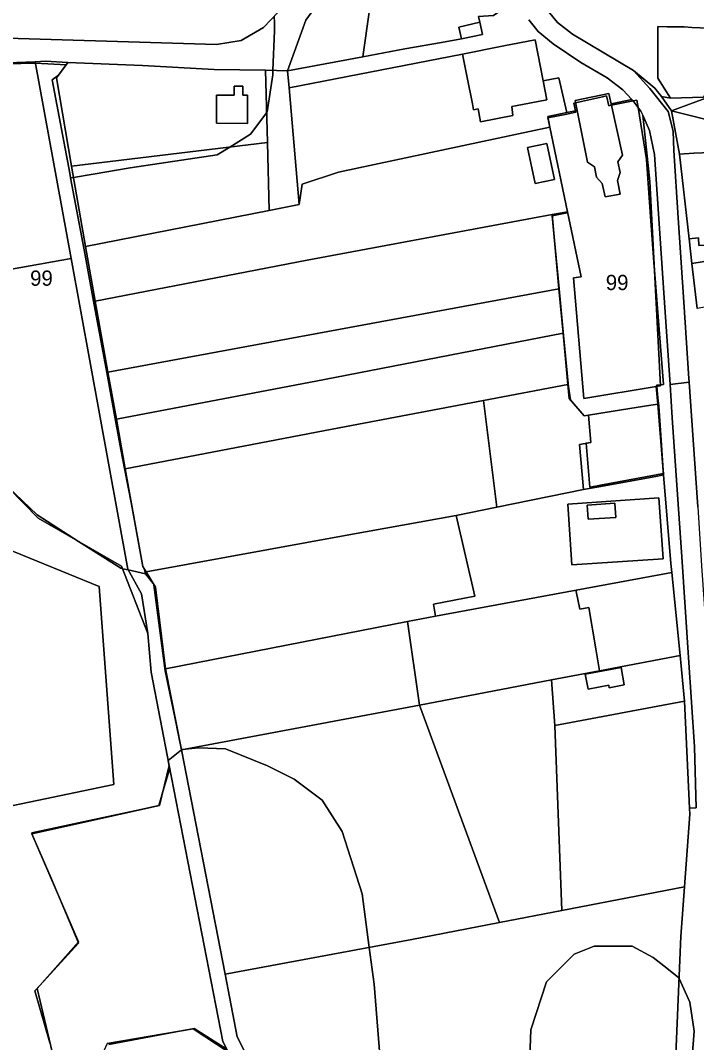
# Model space of a CAD drawing. Extents: x -522079 to -518833, y -1142400 to -1139961.
# Drawn here: x -520504.9 to -520283.3, y -1141508 to -1141173.1 of the extents above; entities that cross this region are included whole.
import ezdxf

# ---------------------------------------------------------------- set-up
doc = ezdxf.new("R2010")
doc.units = 0
for name, color, linetype in [('95560013', 7, 'Continuous'), ('95590013', 7, 'Continuous'), ('95610013', 7, 'Continuous'), ('95630013', 7, 'Continuous'), ('95640013', 7, 'Continuous'), ('95660013', 7, 'Continuous')]:
    doc.layers.add(name, color=color, linetype=linetype)

msp = doc.modelspace()

# ---------------------------------------------------------------- linework, layer by layer
at = {"layer": '95560013'}
for points in [[(-520400.61, -1141222.82), (-520331.36, -1141208.07), (-520325.59, -1141235.8), (-520330.62, -1141236.74), (-520410.93, -1141251.63), (-520480.37, -1141265.08), (-520483.58, -1141247.19), (-520423.33, -1141235.38), (-520413.51, -1141233.43), (-520412.54, -1141226.76)], [(-520423.33, -1141235.38), (-520483.58, -1141247.19), (-520488.14, -1141220.84), (-520423.9, -1141213.13)], [(-520336.17, -1141226.59), (-520329.89, -1141225.22), (-520332.41, -1141213.42), (-520338.66, -1141214.74)], [(-520330.62, -1141236.74), (-520328.39, -1141261.02), (-520407.05, -1141275.59), (-520476.2, -1141288.34), (-520480.37, -1141265.08), (-520410.93, -1141251.63)], [(-520476.2, -1141288.34), (-520407.05, -1141275.59), (-520328.39, -1141261.02), (-520327.05, -1141275.53), (-520405.18, -1141290.79), (-520473.45, -1141303.71)], [(-520405.18, -1141290.79), (-520327.05, -1141275.53), (-520325.5, -1141292.44), (-520353.1, -1141297.63), (-520402.69, -1141307.02), (-520470.52, -1141320.08), (-520473.45, -1141303.71)], [(-520353.1, -1141297.63), (-520348.74, -1141332.58), (-520362.13, -1141335.31), (-520397.21, -1141341.61), (-520463.71, -1141353.8), (-520464.8, -1141352.03), (-520470.52, -1141320.08), (-520402.69, -1141307.02)], [(-520368.84, -1141368.35), (-520378.01, -1141370.07), (-520457.31, -1141385.57), (-520460.62, -1141358.83), (-520463.71, -1141353.8), (-520397.21, -1141341.61), (-520362.13, -1141335.31), (-520355.94, -1141361.7), (-520369.53, -1141364.42)], [(-520457.31, -1141385.57), (-520378.01, -1141370.07), (-520374.09, -1141397.41), (-520388.13, -1141400.07), (-520452.14, -1141412.08)], [(-520329.77, -1141404.14), (-520327.5, -1141464.71), (-520347.92, -1141468.69), (-520374.09, -1141397.41), (-520330.86, -1141389.2)], [(-520347.92, -1141468.69), (-520376.59, -1141474.28), (-520437.82, -1141485.59), (-520452.14, -1141412.08), (-520388.13, -1141400.07), (-520374.09, -1141397.41)], [(-520438.53, -1141507.64), (-520436.83, -1141511), (-520448.25, -1141503.52), (-520476.51, -1141508.33), (-520485.33, -1141527.78), (-520494.54, -1141511.04), (-520499.43, -1141490.33), (-520485.81, -1141474.99), (-520501.13, -1141439.65), (-520459.35, -1141430.33), (-520456.11, -1141417.28)], [(-520287.25, -1141456.97), (-520288.42, -1141473.23), (-520290.19, -1141514.57), (-520290.52, -1141595.71), (-520355.96, -1141608.22), (-520447.63, -1141624.46), (-520447.82, -1141603.5), (-520446.02, -1141598.19), (-520414.26, -1141558.37), (-520414.56, -1141544.64), (-520433.82, -1141506.13), (-520437.82, -1141485.59), (-520376.59, -1141474.28), (-520347.92, -1141468.69), (-520327.5, -1141464.71)]]:
    msp.add_lwpolyline(points, close=True, dxfattribs=at)
at = {"layer": '95590013'}
for points in [[(-520392.71, -1141184.99), (-520390.51, -1141169.6), (-520385.67, -1141162.39), (-520383.02, -1141163.15), (-520382.54, -1141163.3), (-520381.05, -1141158.47), (-520376.18, -1141142.7), (-520369.8, -1141141.08), (-520369.36, -1141147.79), (-520364.41, -1141148.17), (-520363.98, -1141154.29), (-520356.57, -1141153.77), (-520356.59, -1141153.47), (-520347.81, -1141152.92), (-520346.65, -1141169.3), (-520349.86, -1141171.48), (-520354.71, -1141171.83), (-520354.34, -1141173.71), (-520361.25, -1141175.35), (-520360.34, -1141179.18), (-520366.93, -1141180.34), (-520378.86, -1141182.41)], [(-520417.36, -1141189.63), (-520411.3, -1141173.03), (-520402.63, -1141160.92), (-520399.1, -1141160.34), (-520393.37, -1141144.49), (-520399.12, -1141167.44), (-520392.92, -1141168.99), (-520390.51, -1141169.6), (-520392.71, -1141184.99)], [(-520358.48, -1141191.76), (-520356.77, -1141200.4), (-520356.39, -1141202.36), (-520354.91, -1141202.07), (-520354.06, -1141206.38), (-520343.47, -1141204.29), (-520343.86, -1141201.29), (-520342.6, -1141201.05), (-520332.37, -1141199.14), (-520333.6, -1141192.88), (-520328.4, -1141191.92), (-520325.76, -1141203.31), (-520332.09, -1141204.58), (-520331.36, -1141208.07), (-520400.61, -1141222.82), (-520412.54, -1141226.76), (-520413.51, -1141233.43), (-520416.76, -1141195.21), (-520359.99, -1141184.11)], [(-520493.12, -1141191.96), (-520489.31, -1141186.91), (-520464.88, -1141187.85), (-520441.37, -1141189.15), (-520424.53, -1141189.37), (-520423.9, -1141213.13), (-520488.14, -1141220.84)], [(-520423.33, -1141235.38), (-520423.9, -1141213.13), (-520424.53, -1141189.37), (-520417.36, -1141189.63), (-520416.76, -1141195.21), (-520413.51, -1141233.43)], [(-520432.03, -1141197.59), (-520432, -1141194.68), (-520434.8, -1141194.69), (-520434.81, -1141197.59), (-520440.66, -1141197.58), (-520440.68, -1141206.8), (-520430.51, -1141206.85), (-520430.48, -1141197.6)], [(-520281.5, -1141252.18), (-520284.8, -1141252.79), (-520285.74, -1141244.64), (-520282.66, -1141244.34), (-520282.52, -1141246.89), (-520278.03, -1141246.64), (-520278.18, -1141243.9), (-520274.53, -1141243.54), (-520253.62, -1141239.61), (-520253.52, -1141236.33), (-520252.79, -1141247.01), (-520269.34, -1141249.93)], [(-520325.09, -1141296.95), (-520320.11, -1141302.71), (-520318.74, -1141302.49), (-520317.9, -1141311.37), (-520321.67, -1141312.05), (-520320.3, -1141326.77), (-520348.74, -1141332.58), (-520353.1, -1141297.63), (-520325.5, -1141292.44)], [(-520355.94, -1141361.7), (-520362.13, -1141335.31), (-520348.74, -1141332.58), (-520320.3, -1141326.77), (-520313.48, -1141325.64), (-520296.08, -1141322.39), (-520294.09, -1141322.02), (-520291.7, -1141351.03), (-520291.41, -1141353.94), (-520322.8, -1141359.78), (-520368.84, -1141368.35), (-520369.53, -1141364.42)], [(-520295.63, -1141329.58), (-520325.53, -1141331.62), (-520324.17, -1141351.52), (-520294.28, -1141349.48)], [(-520378.01, -1141370.07), (-520368.84, -1141368.35), (-520322.8, -1141359.78), (-520322.7, -1141360.25), (-520321.57, -1141366.05), (-520318.64, -1141365.48), (-520316.31, -1141378.99), (-520315.07, -1141386.2), (-520330.86, -1141389.2), (-520374.09, -1141397.41)], [(-520287.2, -1141396.11), (-520285.62, -1141431.18), (-520285.53, -1141433.12), (-520287.25, -1141456.97), (-520327.5, -1141464.71), (-520329.77, -1141404.14)]]:
    msp.add_lwpolyline(points, close=True, dxfattribs=at)
at = {"layer": '95610013'}
for points in [[(-520432.59, -1141179.7), (-520440.68, -1141181.04), (-520523.78, -1141178.47), (-520526.48, -1141178.44), (-520526.38, -1141166.45), (-520421.91, -1141158.52), (-520408.18, -1141157.48), (-520425.27, -1141175.41)], [(-520534.35, -1141283.17), (-520535.3, -1141264.93), (-520534.84, -1141259.42), (-520488.31, -1141251.1), (-520469.72, -1141352.88), (-520465.21, -1141361), (-520463.1, -1141373.93), (-520471.76, -1141351.9), (-520499.06, -1141336.21), (-520518.61, -1141316.36), (-520539.2, -1141310.09)], [(-520474.23, -1141423.42), (-520512.06, -1141431.3), (-520564.35, -1141443.41), (-520567.96, -1141415.92), (-520573.91, -1141353.97), (-520575.29, -1141345.21), (-520582.4, -1141266.58), (-520545.37, -1141264.63), (-520546.39, -1141287.04), (-520556.25, -1141307.68), (-520549.32, -1141316.76), (-520521.95, -1141327.46), (-520517.94, -1141333.55), (-520509.58, -1141346.13), (-520479.06, -1141358.55)]]:
    msp.add_lwpolyline(points, close=True, dxfattribs=at)
at = {"layer": '95630013'}
for points in [[(-520518.61, -1141316.36), (-520499.06, -1141336.21), (-520471.76, -1141351.9), (-520463.1, -1141373.93), (-520462.06, -1141386.7), (-520456.11, -1141417.28), (-520459.35, -1141430.33), (-520501.13, -1141439.65), (-520485.81, -1141474.99), (-520499.43, -1141490.33), (-520494.54, -1141511.04)], [(-520512.06, -1141431.3), (-520474.23, -1141423.42), (-520479.06, -1141358.55), (-520509.58, -1141346.13)], [(-520476.51, -1141508.33), (-520448.25, -1141503.52), (-520436.83, -1141511)]]:
    msp.add_lwpolyline(points, dxfattribs=at)
at = {"layer": '95640013'}
for points in [[(-520417.36, -1141189.63), (-520392.71, -1141184.99), (-520378.86, -1141182.41), (-520366.93, -1141180.34), (-520360.34, -1141179.18), (-520353.47, -1141177.71), (-520354.34, -1141173.71), (-520354.71, -1141171.83), (-520349.86, -1141171.48), (-520346.65, -1141169.3), (-520347.81, -1141152.92), (-520347.61, -1141152.91), (-520349.11, -1141131.64), (-520357.95, -1141132.21), (-520359.15, -1141132.28), (-520370.32, -1141133), (-520379.87, -1141135.97), (-520380.82, -1141136.27), (-520393.37, -1141144.49), (-520399.1, -1141160.34), (-520402.63, -1141160.92), (-520411.3, -1141173.03)], [(-520354.34, -1141173.71), (-520353.47, -1141177.71), (-520360.34, -1141179.18), (-520361.25, -1141175.35)], [(-520291.52, -1141202.69), (-520294.74, -1141198), (-520291.83, -1141198.59), (-520280.99, -1141198.2), (-520276.81, -1141192.82), (-520265.75, -1141173.55), (-520262.34, -1141173.28), (-520263.7, -1141175.46), (-520265.8, -1141179.08), (-520267.83, -1141182.58), (-520270.74, -1141187.55), (-520275.56, -1141196.82)], [(-520287.4, -1141175.25), (-520284.8, -1141175.38), (-520276.61, -1141175.8), (-520273.02, -1141178.12), (-520276.81, -1141192.82), (-520280.99, -1141198.2), (-520291.83, -1141198.59), (-520295.98, -1141192.02), (-520296.01, -1141175.11), (-520292.9, -1141175.16)], [(-520336.24, -1141179.42), (-520333.6, -1141192.88), (-520332.37, -1141199.14), (-520342.6, -1141201.05), (-520343.86, -1141201.29), (-520343.47, -1141204.29), (-520354.06, -1141206.38), (-520354.91, -1141202.07), (-520356.39, -1141202.36), (-520356.77, -1141200.4), (-520358.48, -1141191.76), (-520359.99, -1141184.11), (-520346.46, -1141181.44)], [(-520535.7, -1141238.47), (-520524.27, -1141187.6), (-520500.08, -1141186.63), (-520488.31, -1141251.1), (-520534.84, -1141259.42), (-520534.05, -1141249.88)], [(-520432.03, -1141197.59), (-520430.48, -1141197.6), (-520430.51, -1141206.85), (-520440.68, -1141206.8), (-520440.66, -1141197.58), (-520434.81, -1141197.59), (-520434.8, -1141194.69), (-520432, -1141194.68)], [(-520309.23, -1141225.55), (-520308.37, -1141230.04), (-520313.3, -1141230.91), (-520314.28, -1141226.51), (-520316.06, -1141224.47), (-520316.76, -1141221.12), (-520319.07, -1141219.54), (-520322.39, -1141202.63), (-520323.1, -1141199.37), (-520312, -1141197.1), (-520311.28, -1141200.4), (-520307.6, -1141217.21), (-520309.05, -1141219.45), (-520308.34, -1141222.91)], [(-520275.56, -1141196.82), (-520280.13, -1141205.59), (-520291.52, -1141202.69)], [(-520323.62, -1141257.49), (-520321.16, -1141257.11), (-520325.59, -1141235.8), (-520331.36, -1141208.07), (-520332.09, -1141204.58), (-520325.76, -1141203.31), (-520322.39, -1141202.63), (-520319.07, -1141219.54), (-520316.76, -1141221.12), (-520316.06, -1141224.47), (-520314.28, -1141226.51), (-520313.3, -1141230.91), (-520308.37, -1141230.04), (-520309.23, -1141225.55), (-520308.34, -1141222.91), (-520309.05, -1141219.45), (-520307.6, -1141217.21), (-520311.28, -1141200.4), (-520304.49, -1141199.02), (-520304.21, -1141199.32), (-520301.55, -1141202.8), (-520300.95, -1141204.15), (-520298.61, -1141225.85), (-520295.11, -1141292.82), (-520296.48, -1141293.05), (-520320.29, -1141297.03)], [(-520285.62, -1141431.18), (-520287.2, -1141396.11), (-520288.69, -1141381.19), (-520291.41, -1141353.94), (-520291.7, -1141351.03), (-520294.09, -1141322.02), (-520296, -1141298.82), (-520296.48, -1141293.05), (-520295.11, -1141292.82), (-520298.61, -1141225.85), (-520300.95, -1141204.15), (-520298.67, -1141209.18), (-520297.11, -1141217.05), (-520293.97, -1141262.32), (-520291.98, -1141292.42), (-520291.26, -1141303.35), (-520288.07, -1141348.91), (-520285.88, -1141381.79), (-520283.95, -1141411.07), (-520283.46, -1141431.12)], [(-520336.17, -1141226.59), (-520338.66, -1141214.74), (-520332.41, -1141213.42), (-520329.89, -1141225.22)], [(-520252.29, -1141220.01), (-520254.68, -1141219.42), (-520253.52, -1141236.33), (-520253.62, -1141239.61), (-520274.53, -1141243.54), (-520278.18, -1141243.9), (-520278.03, -1141246.64), (-520282.52, -1141246.89), (-520282.66, -1141244.34), (-520285.74, -1141244.64), (-520288.93, -1141216.9), (-520284.22, -1141216.65), (-520265.11, -1141215.87), (-520258.35, -1141216.74), (-520252.46, -1141217.61)], [(-520323.62, -1141257.49), (-520320.29, -1141297.03), (-520296.48, -1141293.05), (-520296, -1141298.82), (-520298.25, -1141299.19), (-520307.88, -1141300.74), (-520318.74, -1141302.49), (-520320.11, -1141302.71), (-520325.09, -1141296.95), (-520325.5, -1141292.44), (-520327.05, -1141275.53), (-520328.39, -1141261.02), (-520330.62, -1141236.74), (-520325.59, -1141235.8), (-520321.16, -1141257.11)], [(-520253.23, -1141262.13), (-520266.64, -1141264.52), (-520278.73, -1141266.68), (-520283.12, -1141267.46), (-520284.8, -1141252.79), (-520281.5, -1141252.18), (-520269.34, -1141249.93), (-520252.79, -1141247.01), (-520250.1, -1141261.57)], [(-520321.67, -1141312.05), (-520317.9, -1141311.37), (-520318.74, -1141302.49), (-520307.88, -1141300.74), (-520298.25, -1141299.19), (-520296, -1141298.82), (-520294.09, -1141322.02), (-520296.08, -1141322.39), (-520313.48, -1141325.64), (-520320.3, -1141326.77)], [(-520325.53, -1141331.62), (-520295.63, -1141329.58), (-520294.28, -1141349.48), (-520324.17, -1141351.52)], [(-520310.06, -1141331.33), (-520319.11, -1141331.93), (-520318.81, -1141336.57), (-520309.76, -1141335.98)], [(-520309.76, -1141335.98), (-520318.81, -1141336.57), (-520319.11, -1141331.93), (-520310.06, -1141331.33)], [(-520321.57, -1141366.05), (-520322.7, -1141360.25), (-520322.8, -1141359.78), (-520291.41, -1141353.94), (-520288.69, -1141381.19), (-520315.07, -1141386.2), (-520316.31, -1141378.99), (-520318.64, -1141365.48)], [(-520330.86, -1141389.2), (-520315.07, -1141386.2), (-520288.69, -1141381.19), (-520287.2, -1141396.11), (-520329.77, -1141404.14)], [(-520319.76, -1141387.31), (-520318.87, -1141392.21), (-520312.06, -1141390.95), (-520311.92, -1141391.74), (-520306.98, -1141390.8), (-520307.96, -1141385.14)], [(-520311.92, -1141391.74), (-520312.06, -1141390.95), (-520318.87, -1141392.21), (-520319.76, -1141387.31), (-520307.96, -1141385.14), (-520306.98, -1141390.8)]]:
    msp.add_lwpolyline(points, close=True, dxfattribs=at)
for points in [[(-520523.78, -1141178.47), (-520440.68, -1141181.04), (-520432.59, -1141179.7), (-520425.27, -1141175.41), (-520408.18, -1141157.48)], [(-520333.5, -1141168.21), (-520328.85, -1141173.77), (-520323.9, -1141177.63), (-520313.7, -1141183.68), (-520304, -1141189.53), (-520298.66, -1141195.42), (-520292.63, -1141202.98), (-520290.93, -1141209.43), (-520290.72, -1141215.76), (-520289.28, -1141237.74), (-520287.43, -1141265.4), (-520285.78, -1141290.4), (-520285.69, -1141291.6), (-520291.98, -1141292.42), (-520293.97, -1141262.32), (-520297.11, -1141217.05), (-520298.67, -1141209.18), (-520300.95, -1141204.15), (-520301.55, -1141202.8), (-520304.21, -1141199.32), (-520304.49, -1141199.02), (-520307.43, -1141195.9), (-520312.59, -1141191.95), (-520321.21, -1141186.85), (-520330.27, -1141180.78), (-520335.19, -1141176.69), (-520338.22, -1141172.95)], [(-520263.33, -1141170.08), (-520262.34, -1141173.28), (-520265.75, -1141173.55), (-520276.61, -1141175.8), (-520284.8, -1141175.38), (-520287.4, -1141175.25), (-520292.9, -1141175.16), (-520296.01, -1141175.11), (-520295.98, -1141192.02), (-520291.83, -1141198.59), (-520294.74, -1141198), (-520297.02, -1141195.35), (-520304, -1141189.53), (-520313.7, -1141183.68), (-520323.9, -1141177.63), (-520328.85, -1141173.77), (-520333.5, -1141168.21)], [(-520338.22, -1141172.95), (-520335.19, -1141176.69), (-520330.27, -1141180.78), (-520321.21, -1141186.85), (-520312.59, -1141191.95), (-520307.43, -1141195.9), (-520304.49, -1141199.02), (-520311.28, -1141200.4), (-520312, -1141197.1), (-520323.1, -1141199.37), (-520322.39, -1141202.63), (-520325.76, -1141203.31), (-520328.4, -1141191.92), (-520333.6, -1141192.88), (-520336.24, -1141179.42), (-520346.46, -1141181.44), (-520359.99, -1141184.11), (-520416.76, -1141195.21), (-520417.36, -1141189.63), (-520424.53, -1141189.37), (-520441.37, -1141189.15), (-520464.88, -1141187.85), (-520489.31, -1141186.91), (-520496.7, -1141186.49), (-520500.08, -1141186.63), (-520524.27, -1141187.6)], [(-520436.83, -1141511), (-520438.53, -1141507.64), (-520456.11, -1141417.28), (-520462.06, -1141386.7), (-520463.1, -1141373.93), (-520465.21, -1141361), (-520469.72, -1141352.88), (-520488.31, -1141251.1), (-520500.08, -1141186.63), (-520496.7, -1141186.49), (-520489.31, -1141186.91), (-520493.12, -1141191.96), (-520488.14, -1141220.84), (-520483.58, -1141247.19), (-520480.37, -1141265.08), (-520476.2, -1141288.34), (-520473.45, -1141303.71), (-520470.52, -1141320.08), (-520464.8, -1141352.03), (-520463.71, -1141353.8), (-520460.62, -1141358.83), (-520457.31, -1141385.57), (-520452.14, -1141412.08), (-520437.82, -1141485.59), (-520433.82, -1141506.13), (-520414.56, -1141544.64)], [(-520282.86, -1141332.45), (-520284.36, -1141310.52), (-520285.69, -1141291.6), (-520285.78, -1141290.4), (-520287.43, -1141265.4), (-520289.28, -1141237.74), (-520290.72, -1141215.76), (-520290.93, -1141209.43), (-520292.63, -1141202.98), (-520298.66, -1141195.42), (-520304, -1141189.53), (-520297.02, -1141195.35), (-520294.74, -1141198), (-520291.52, -1141202.69), (-520288.93, -1141216.9), (-520285.74, -1141244.64), (-520284.8, -1141252.79), (-520283.12, -1141267.46)], [(-520265.11, -1141215.87), (-520284.22, -1141216.65), (-520288.93, -1141216.9), (-520291.52, -1141202.69), (-520280.13, -1141205.59)], [(-520290.19, -1141514.57), (-520288.42, -1141473.23), (-520287.25, -1141456.97), (-520285.53, -1141433.12), (-520285.62, -1141431.18), (-520283.46, -1141431.12), (-520283.95, -1141411.07), (-520285.88, -1141381.79), (-520288.07, -1141348.91), (-520291.26, -1141303.35), (-520291.98, -1141292.42), (-520285.69, -1141291.6), (-520284.36, -1141310.52), (-520282.86, -1141332.45), (-520281.66, -1141351.81), (-520280.36, -1141370.5), (-520279.11, -1141388.58), (-520278.27, -1141410.62), (-520277.86, -1141423.4), (-520277.92, -1141430.99), (-520274.48, -1141431.01), (-520274.69, -1141472.35), (-520275.67, -1141487.93), (-520277.2, -1141512.43)]]:
    msp.add_lwpolyline(points, dxfattribs=at)
at = {"layer": '95660013'}
for points in [[(-520421.78, -1141171.75), (-520421.57, -1141173.87), (-520421.67, -1141176.52), (-520422.13, -1141189.45), (-520422.18, -1141190.93), (-520424, -1141203.11), (-520424.16, -1141203.33), (-520429.47, -1141210.43), (-520436.3, -1141214.61), (-520440.4, -1141217.13), (-520468.94, -1141221.4), (-520481.02, -1141223.43), (-520487.5, -1141224.52), (-520488.45, -1141224.68), (-520488.74, -1141223.16), (-520494.47, -1141192.6), (-520492.42, -1141191.02), (-520489.87, -1141187.64), (-520499.98, -1141187.16), (-520500.85, -1141187.11), (-520524.31, -1141187.79)], [(-520386.37, -1141521.76), (-520388.92, -1141488.89), (-520390.55, -1141476.86), (-520392.92, -1141459.3), (-520399.48, -1141438.85), (-520406.03, -1141428.62), (-520415.13, -1141421.68), (-520423.87, -1141417.3), (-520437.71, -1141411.82), (-520446.45, -1141411.45), (-520447.63, -1141411.58), (-520451.93, -1141412.04), (-520452.04, -1141412.05), (-520452.14, -1141412.08), (-520453.59, -1141404.63), (-520453.61, -1141404.55), (-520457.43, -1141386.23), (-520461.13, -1141357.99), (-520461.24, -1141357.81), (-520461.4, -1141357.57), (-520463.05, -1141355.49), (-520463.9, -1141354.41), (-520464.18, -1141353.04), (-520464.8, -1141352.03), (-520468.46, -1141331.58), (-520470.68, -1141320.48), (-520471.96, -1141313.67), (-520473.73, -1141304.21), (-520476.59, -1141288.49), (-520480.92, -1141265.11), (-520484.03, -1141248.32), (-520488.45, -1141224.68), (-520487.5, -1141224.52), (-520481.02, -1141223.43), (-520468.94, -1141221.4), (-520440.4, -1141217.13), (-520436.3, -1141214.61), (-520429.47, -1141210.43), (-520424.16, -1141203.33), (-520424, -1141203.11), (-520422.18, -1141190.93), (-520422.13, -1141189.45), (-520421.67, -1141176.52), (-520421.57, -1141173.87), (-520421.78, -1141171.75)], [(-520524.31, -1141187.79), (-520500.85, -1141187.11), (-520499.98, -1141187.16), (-520489.87, -1141187.64), (-520492.42, -1141191.02), (-520494.47, -1141192.6), (-520488.74, -1141223.16), (-520488.45, -1141224.68), (-520484.03, -1141248.32), (-520480.92, -1141265.11), (-520476.59, -1141288.49), (-520473.73, -1141304.21), (-520471.96, -1141313.67), (-520470.68, -1141320.48), (-520468.46, -1141331.58), (-520464.8, -1141352.03), (-520464.18, -1141353.04), (-520463.9, -1141354.41), (-520469.56, -1141353.16), (-520471.42, -1141352.75), (-520472, -1141352.62), (-520485.86, -1141343.79), (-520499.45, -1141335.14), (-520511.59, -1141323.48)], [(-520511.59, -1141323.48), (-520499.45, -1141335.14), (-520485.86, -1141343.79), (-520472, -1141352.62), (-520471.42, -1141352.75), (-520469.56, -1141353.16), (-520463.9, -1141354.41), (-520463.05, -1141355.49), (-520461.4, -1141357.57), (-520461.24, -1141357.81), (-520461.13, -1141357.99), (-520457.43, -1141386.23), (-520453.61, -1141404.55), (-520453.59, -1141404.63), (-520452.14, -1141412.08), (-520456.44, -1141415.59), (-520456.52, -1141415.65), (-520456.16, -1141417.47), (-520455.97, -1141418.42), (-520456.53, -1141420.29), (-520458.4, -1141426.49), (-520458.78, -1141427.76), (-520459.56, -1141430.38), (-520463.88, -1141431.34), (-520501.15, -1141439.31), (-520501.02, -1141439.62), (-520501.13, -1141439.65), (-520494.84, -1141454.15), (-520485.93, -1141475.12), (-520485.82, -1141475.39), (-520498.51, -1141489.29), (-520500.16, -1141491.1), (-520495.24, -1141508.09)], [(-520495.24, -1141508.09), (-520500.16, -1141491.1), (-520498.51, -1141489.29), (-520485.82, -1141475.39), (-520485.93, -1141475.12), (-520494.84, -1141454.15), (-520501.13, -1141439.65), (-520501.02, -1141439.62), (-520501.15, -1141439.31), (-520463.88, -1141431.34), (-520459.56, -1141430.38), (-520458.78, -1141427.76), (-520458.4, -1141426.49), (-520456.53, -1141420.29), (-520455.97, -1141418.42), (-520456.16, -1141417.47), (-520456.52, -1141415.65), (-520456.44, -1141415.59), (-520452.14, -1141412.08), (-520452.04, -1141412.05), (-520451.93, -1141412.04), (-520447.63, -1141411.58), (-520446.45, -1141411.45), (-520437.71, -1141411.82), (-520423.87, -1141417.3), (-520415.13, -1141421.68), (-520406.03, -1141428.62), (-520399.48, -1141438.85), (-520392.92, -1141459.3), (-520390.55, -1141476.86), (-520388.92, -1141488.89), (-520386.37, -1141521.76)], [(-520286.61, -1141536.74), (-520284.06, -1141504.23), (-520285.52, -1141494.73), (-520289.01, -1141487.02), (-520289.16, -1141486.7), (-520293.99, -1141482.9), (-520296.03, -1141481.3), (-520297.53, -1141480.12), (-520304.45, -1141476.47), (-520316.83, -1141476.47), (-520323.38, -1141479.02), (-520332.48, -1141488.16), (-520337.58, -1141503.86), (-520338.31, -1141521.4)], [(-520338.31, -1141521.4), (-520337.58, -1141503.86), (-520332.48, -1141488.16), (-520323.38, -1141479.02), (-520316.83, -1141476.47), (-520304.45, -1141476.47), (-520297.53, -1141480.12), (-520296.03, -1141481.3), (-520293.99, -1141482.9), (-520289.16, -1141486.7), (-520289.01, -1141487.02), (-520285.52, -1141494.73), (-520284.06, -1141504.23), (-520286.61, -1141536.74)], [(-520475.95, -1141508.61), (-520452.79, -1141504.29), (-520447.92, -1141503.38), (-520437.23, -1141510.21)], [(-520437.23, -1141510.21), (-520447.92, -1141503.38), (-520452.79, -1141504.29), (-520475.95, -1141508.61)]]:
    msp.add_lwpolyline(points, dxfattribs=at)
for points in [[(-520312.79, -1141197.82), (-520312.03, -1141201.04), (-520311.18, -1141200.87), (-520304.11, -1141199.45), (-520302.86, -1141199.2), (-520302.66, -1141200.45), (-520302.48, -1141201.59), (-520299.7, -1141218.66), (-520298.58, -1141234.31), (-520297.17, -1141253.88), (-520297.09, -1141254.93), (-520296.65, -1141260.49), (-520294.1, -1141292.44), (-520295.12, -1141292.53), (-520296.37, -1141292.63), (-520296.33, -1141293.02), (-520295.98, -1141296.72), (-520295.71, -1141299.5), (-520295.03, -1141308.97), (-520294.21, -1141320.54), (-520294.14, -1141321.52), (-520295.96, -1141321.86), (-520297.05, -1141322.07), (-520314.79, -1141325.4), (-520316.42, -1141325.7), (-520318.26, -1141326.04), (-520319.44, -1141311.65), (-520317.9, -1141311.37), (-520318.74, -1141302.49), (-520320.11, -1141302.71), (-520324.21, -1141297.97), (-520324.61, -1141297.39), (-520325.24, -1141293.13), (-520326.88, -1141276.37), (-520328.29, -1141261.01), (-520329.94, -1141244.17), (-520330.58, -1141237.17), (-520325.66, -1141236.16), (-520325.73, -1141235.83), (-520325.59, -1141235.8), (-520331.36, -1141208.07), (-520331.99, -1141205.04), (-520326.41, -1141203.92), (-520322.84, -1141203.2), (-520322.95, -1141202.74), (-520323.52, -1141200.27), (-520322.93, -1141200.13), (-520314.17, -1141198.13)], [(-520324.21, -1141297.97), (-520320.11, -1141302.71), (-520318.74, -1141302.49), (-520317.9, -1141311.37), (-520319.44, -1141311.65), (-520318.26, -1141326.04), (-520316.42, -1141325.7), (-520314.79, -1141325.4), (-520297.05, -1141322.07), (-520295.96, -1141321.86), (-520294.14, -1141321.52), (-520294.21, -1141320.54), (-520295.03, -1141308.97), (-520295.71, -1141299.5), (-520295.98, -1141296.72), (-520296.33, -1141293.02), (-520296.37, -1141292.63), (-520295.12, -1141292.53), (-520294.1, -1141292.44), (-520296.65, -1141260.49), (-520297.09, -1141254.93), (-520297.17, -1141253.88), (-520298.58, -1141234.31), (-520299.7, -1141218.66), (-520302.48, -1141201.59), (-520302.66, -1141200.45), (-520302.86, -1141199.2), (-520304.11, -1141199.45), (-520311.18, -1141200.87), (-520312.03, -1141201.04), (-520312.79, -1141197.82), (-520314.17, -1141198.13), (-520322.93, -1141200.13), (-520323.52, -1141200.27), (-520322.95, -1141202.74), (-520322.84, -1141203.2), (-520326.41, -1141203.92), (-520331.99, -1141205.04), (-520331.36, -1141208.07), (-520325.59, -1141235.8), (-520325.73, -1141235.83), (-520325.66, -1141236.16), (-520330.58, -1141237.17), (-520329.94, -1141244.17), (-520328.29, -1141261.01), (-520326.88, -1141276.37), (-520325.24, -1141293.13), (-520324.61, -1141297.39)]]:
    msp.add_lwpolyline(points, close=True, dxfattribs=at)

# ---------------------------------------------------------------- texts
for p in [(-520501.72, -1141260.05), (-520313.04, -1141261.47)]:
    msp.add_text('99', height=5, rotation=360, dxfattribs=at).set_placement(p)

doc.saveas('drawing.dxf')
